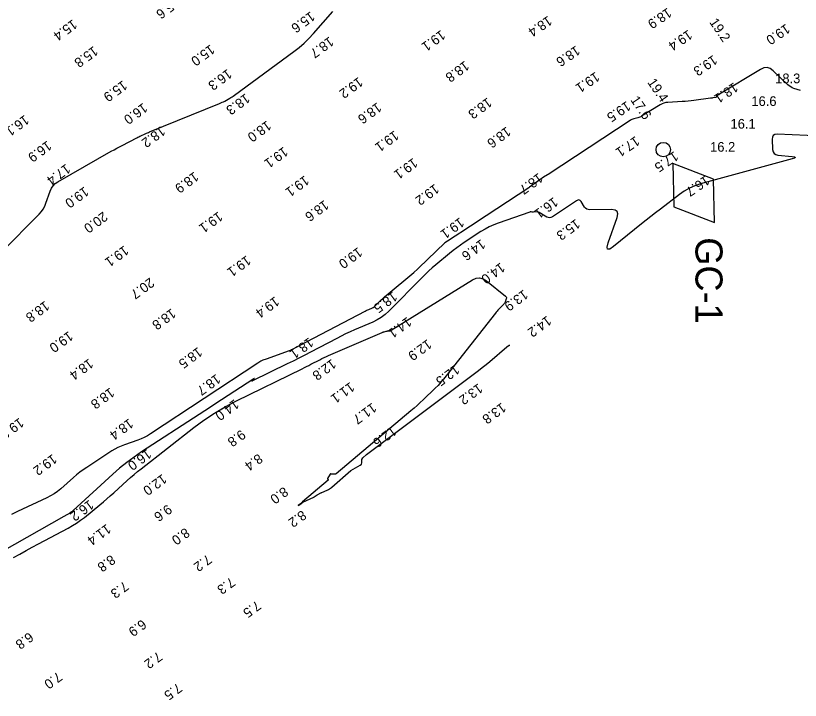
# Model space of a CAD drawing. Extents: x 824616 to 827440, y 158441 to 163197.
# Drawn here: x 826199.3 to 826605.2, y 159460.1 to 159814.3 of the extents above; entities that cross this region are included whole.
import ezdxf

# ---------------------------------------------------------------- set-up
doc = ezdxf.new("R2010")
doc.units = 0
for name, color, linetype in [('V-CHAN-CONT-EL14', 7, 'Continuous'), ('V-CHAN-CONT-EL16', 7, 'Continuous'), ('V-CHAN-CONT-EL18', 7, 'Continuous'), ('V-CHAN-NAID', 7, 'Continuous'), ('V-TOPO-SOUN', 7, 'Continuous')]:
    doc.layers.add(name, color=color, linetype=linetype)

msp = doc.modelspace()

# ---------------------------------------------------------------- linework, layer by layer
at = {"layer": 'V-CHAN-CONT-EL14'}
msp.add_lwpolyline([(826198.15, 159533.93), (826201.38, 159535.74), (826204.61, 159537.53), (826207.86, 159539.29), (826211.11, 159541.04), (826226.44, 159549.2), (826228.62, 159550.43), (826230.74, 159551.76), (826232.79, 159553.19), (826234.77, 159554.72), (826242.8, 159561.24), (826244.63, 159562.74), (826246.43, 159564.27), (826248.21, 159565.82), (826249.96, 159567.41), (826256.93, 159573.79), (826258.68, 159575.37), (826260.47, 159576.91), (826262.29, 159578.42), (826264.14, 159579.89), (826291.4, 159601.16), (826296.65, 159605.05), (826302.09, 159608.65), (826307.7, 159611.96), (826313.5, 159614.98), (826347.48, 159631.64), (826348.63, 159632.2), (826349.77, 159632.78), (826350.9, 159633.36), (826352.04, 159633.94), (826356.56, 159636.31), (826357.69, 159636.89), (826358.84, 159637.45), (826360, 159637.98), (826361.16, 159638.5), (826388.81, 159650.38), (826389.06, 159650.48), (826389.32, 159650.58), (826389.58, 159650.66), (826389.84, 159650.74), (826391, 159651.06), (826391.22, 159651.11), (826391.43, 159651.15), (826391.65, 159651.19), (826391.86, 159651.21), (826392.74, 159651.27), (826392.96, 159651.3), (826393.16, 159651.35), (826393.36, 159651.43), (826393.55, 159651.53), (826435.55, 159677.56), (826437.44, 159678.42), (826439.29, 159678.63), (826441.1, 159678.2), (826442.87, 159677.11), (826452.68, 159669.22), (826452.97, 159668.92), (826453.13, 159668.58), (826453.17, 159668.21), (826453.08, 159667.81), (826452.46, 159666.12), (826452.28, 159665.71), (826452.06, 159665.33), (826451.8, 159664.97), (826451.5, 159664.65), (826449.23, 159662.43), (826448.76, 159661.95), (826448.3, 159661.45), (826447.85, 159660.94), (826447.43, 159660.41), (826422, 159627.89), (826420.65, 159626.22), (826419.24, 159624.61), (826417.78, 159623.04), (826416.26, 159621.53), (826410.09, 159615.57), (826408.53, 159614.1), (826406.95, 159612.65), (826405.34, 159611.23), (826403.71, 159609.83), (826365.05, 159577.31), (826364.87, 159577.19), (826364.67, 159577.1), (826364.47, 159577.04), (826364.25, 159577.03), (826363.11, 159577.04), (826363, 159577.05), (826362.89, 159577.06), (826362.79, 159577.08), (826362.68, 159577.1), (826362.26, 159577.2), (826362.16, 159577.21), (826362.07, 159577.19), (826362, 159577.15), (826361.94, 159577.07), (826360.61, 159574.87), (826360.57, 159574.79), (826360.56, 159574.71), (826360.58, 159574.63), (826360.64, 159574.55), (826360.9, 159574.26), (826360.94, 159574.19), (826360.96, 159574.12), (826360.94, 159574.05), (826360.88, 159573.99), (826347.68, 159562.75), (826346.02, 159561.33), (826345.48, 159560.84), (826346.06, 159561.28), (826347.76, 159562.65), (826353.59, 159565.23), (826353.71, 159565.31), (826355.27, 159566.37), (826357.41, 159567.63), (826357.36, 159567.5), (826358, 159567.83), (826358.57, 159567.97), (826361.13, 159569.22), (826362.68, 159570.26), (826362.82, 159570.31), (826372.7, 159578.96), (826377.45, 159581.71), (826378.16, 159582.23), (826378.31, 159582.91), (826378.31, 159583.36), (826378.35, 159583.73), (826378.31, 159584.23), (826378.34, 159584.62), (826378.82, 159585.52), (826380.79, 159587.18), (826436.72, 159629.17), (826438.7, 159630.69), (826440.66, 159632.23), (826442.6, 159633.8), (826444.52, 159635.4), (826453.38, 159642.91), (826454.66, 159643.81), (826454.96, 159643.85)], dxfattribs=at)
at = {"layer": 'V-CHAN-CONT-EL16'}
msp.add_lwpolyline([(826616.44, 159752.06), (826593.19, 159752.93), (826592.04, 159752.81), (826591.24, 159752.34), (826590.78, 159751.54), (826590.67, 159750.39), (826590.91, 159745.1), (826591.13, 159743.93), (826591.67, 159743.05), (826592.51, 159742.47), (826593.67, 159742.18), (826600.98, 159741.42), (826602.23, 159741.21), (826602.66, 159740.94), (826602.28, 159740.6), (826601.08, 159740.2), (826553.51, 159727.23), (826550.59, 159726.29), (826547.8, 159725.07), (826545.15, 159723.58), (826542.63, 159721.83), (826532.81, 159714.28), (826530.37, 159712.38), (826527.93, 159710.47), (826525.5, 159708.55), (826523.09, 159706.61), (826508.58, 159694.9), (826506.64, 159693.59), (826505.54, 159693.48), (826505.28, 159694.55), (826505.86, 159696.82), (826510.43, 159709.93), (826510.79, 159711.71), (826510.42, 159712.98), (826509.34, 159713.73), (826507.54, 159713.97), (826496.26, 159713.88), (826495.46, 159713.96), (826494.75, 159714.22), (826494.14, 159714.66), (826493.63, 159715.28), (826491.76, 159718.12), (826491.26, 159718.68), (826490.7, 159718.95), (826490.09, 159718.92), (826489.41, 159718.59), (826476.95, 159710.23), (826476.22, 159709.86), (826475.48, 159709.72), (826474.74, 159709.82), (826473.99, 159710.15), (826470.05, 159712.48), (826469.76, 159712.63), (826469.45, 159712.73), (826469.14, 159712.78), (826468.81, 159712.78), (826467.13, 159712.66), (826466.98, 159712.66), (826466.83, 159712.66), (826466.67, 159712.67), (826466.52, 159712.68), (826465.91, 159712.76), (826465.76, 159712.77), (826465.61, 159712.76), (826465.46, 159712.74), (826465.32, 159712.7), (826448.9, 159707.03), (826446.56, 159706.14), (826444.29, 159705.11), (826442.1, 159703.94), (826439.97, 159702.63), (826431.32, 159696.94), (826429.38, 159695.62), (826427.48, 159694.25), (826425.62, 159692.83), (826423.79, 159691.35), (826416.58, 159685.35), (826414.79, 159683.82), (826413.05, 159682.26), (826411.34, 159680.65), (826409.67, 159679.01), (826392.28, 159661.42), (826390.41, 159659.71), (826388.41, 159658.19), (826386.27, 159656.88), (826384, 159655.77), (826374.61, 159651.74), (826372.27, 159650.71), (826369.96, 159649.63), (826367.66, 159648.52), (826365.39, 159647.35), (826351.83, 159640.26), (826348.81, 159638.7), (826345.78, 159637.15), (826342.74, 159635.62), (826339.69, 159634.12), (826321.76, 159625.33), (826321.54, 159625.24), (826321.45, 159625.23), (826321.48, 159625.32), (826321.64, 159625.5), (826322.54, 159626.39), (826322.71, 159626.56), (826322.75, 159626.63), (826322.67, 159626.61), (826322.47, 159626.48), (826305.74, 159615.46), (826302.86, 159613.57), (826299.98, 159611.68), (826297.1, 159609.8), (826294.21, 159607.92), (826264.38, 159588.6), (826260.48, 159585.95), (826256.69, 159583.15), (826253.03, 159580.19), (826249.48, 159577.07), (826228.92, 159558.23), (826228.75, 159558.08), (826228.58, 159557.92), (826228.4, 159557.78), (826228.22, 159557.63), (826227.52, 159557.06), (826227.34, 159556.92), (826227.15, 159556.79), (826226.96, 159556.67), (826226.76, 159556.55), (826225.37, 159555.81), (826225.07, 159555.65), (826224.77, 159555.49), (826224.48, 159555.33), (826224.18, 159555.16), (826179.28, 159529.82)], dxfattribs=at)
at = {"layer": 'V-CHAN-CONT-EL18'}
for points in [[(826191.93, 159691.89), (826211.47, 159711.7), (826212.56, 159712.94), (826213.5, 159714.27), (826214.28, 159715.7), (826214.91, 159717.23), (826217.1, 159723.53), (826217.76, 159725.02), (826218.64, 159726.31), (826219.75, 159727.42), (826221.09, 159728.34), (826248.73, 159744.15), (826250.13, 159744.94), (826251.54, 159745.72), (826252.96, 159746.48), (826254.38, 159747.23), (826261.85, 159751.13), (826262.4, 159751.41), (826262.95, 159751.68), (826263.51, 159751.94), (826264.06, 159752.2), (826266.31, 159753.22), (826266.87, 159753.47), (826267.43, 159753.72), (826268, 159753.96), (826268.57, 159754.19), (826304.79, 159768.9), (826305.47, 159769.19), (826306.13, 159769.49), (826306.78, 159769.81), (826307.43, 159770.15), (826309.99, 159771.56), (826310.62, 159771.92), (826311.24, 159772.3), (826311.85, 159772.7), (826312.45, 159773.12), (826343.1, 159795.74), (826345.84, 159797.88), (826348.46, 159800.16), (826350.95, 159802.57), (826353.31, 159805.13), (826363.26, 159816.5)], [(826605.35, 159775.6), (826601.88, 159776.73), (826601.04, 159777.06), (826600.25, 159777.48), (826599.51, 159777.98), (826598.82, 159778.56), (826591.15, 159785.85), (826589.61, 159786.97), (826588.01, 159787.45), (826586.35, 159787.31), (826584.61, 159786.55), (826563.41, 159773.65), (826563.29, 159773.57), (826563.17, 159773.51), (826563.04, 159773.44), (826562.92, 159773.38), (826562.34, 159773.11), (826562.25, 159773.06), (826562.17, 159773), (826562.09, 159772.93), (826562.02, 159772.85), (826561.68, 159772.4), (826561.66, 159772.37), (826561.65, 159772.34), (826561.64, 159772.31), (826561.64, 159772.27), (826561.63, 159772.14), (826561.63, 159772.11), (826561.61, 159772.09), (826561.59, 159772.07), (826561.56, 159772.06), (826559.91, 159771.78), (826559.62, 159771.73), (826559.33, 159771.69), (826559.05, 159771.64), (826558.76, 159771.6), (826550.2, 159770.43), (826548.67, 159770.24), (826547.15, 159770.08), (826545.61, 159769.95), (826544.08, 159769.85), (826536.6, 159769.46), (826535.58, 159769.34), (826534.6, 159769.1), (826533.66, 159768.74), (826532.75, 159768.26), (826523.09, 159762.31), (826522.63, 159762.05), (826522.16, 159761.83), (826521.67, 159761.64), (826521.16, 159761.49), (826519.1, 159760.95), (826518.6, 159760.8), (826518.11, 159760.61), (826517.64, 159760.37), (826517.19, 159760.1), (826474.83, 159732.2), (826474.36, 159731.97), (826472.4, 159730.85), (826470.37, 159729.38)], [(826470.37, 159729.38), (826465.08, 159725.55), (826464.67, 159725.19), (826437.23, 159707.11), (826435.9, 159706.24), (826434.58, 159705.37), (826433.26, 159704.51), (826431.93, 159703.65), (826426.63, 159700.21), (826425.3, 159699.35), (826423.98, 159698.49), (826422.66, 159697.62), (826421.33, 159696.75), (826407.78, 159683.83)], [(826340.78, 159640.98), (826340.83, 159640.98), (826340.94, 159641.03), (826341.54, 159641.32), (826341.68, 159641.39), (826341.83, 159641.46), (826341.97, 159641.54), (826342.12, 159641.61), (826380.11, 159661.48), (826380.56, 159661.71), (826381.02, 159661.93), (826381.49, 159662.15), (826381.95, 159662.36), (826383.83, 159663.16), (826384.29, 159663.38), (826384.71, 159663.65), (826385.11, 159663.95), (826385.49, 159664.29), (826388.41, 159667.25), (826389.03, 159667.86), (826389.65, 159668.45), (826390.3, 159669.02), (826390.95, 159669.58), (826405.29, 159681.51), (826407.21, 159683.17), (826407.71, 159683.75), (826407.78, 159683.83)], [(826340.78, 159640.98), (826328.83, 159636.67), (826327.19, 159636.07), (826326.02, 159635.53), (826324.58, 159634.55), (826268.97, 159597.92), (826267.41, 159596.96), (826265.8, 159596.11), (826264.14, 159595.35), (826262.43, 159594.7), (826255.49, 159592.3), (826253.78, 159591.65), (826252.12, 159590.89), (826250.52, 159590.03), (826248.96, 159589.08), (826236.01, 159580.56), (826234.21, 159579.33), (826232.46, 159578.04), (826230.75, 159576.69), (826229.09, 159575.29), (826222.53, 159569.54), (826220.85, 159568.16), (826219.08, 159566.92), (826217.24, 159565.8), (826215.31, 159564.8), (826200.24, 159557.7), (826197.1, 159556.15)]]:
    msp.add_lwpolyline(points, dxfattribs=at)
at = {"layer": 'V-CHAN-NAID'}
msp.add_lwpolyline([(826539.3, 159737.86), (826539.81, 159715.39), (826560.75, 159707.22), (826560.23, 159729.69)], close=True, dxfattribs=at)
msp.add_circle((826534.29, 159745.01), 3.74, dxfattribs=at)

# ---------------------------------------------------------------- texts
msp.add_text('GC-1', height=14, rotation=270, dxfattribs=at).set_placement((826550.97, 159699.65))
at = {"layer": 'V-TOPO-SOUN'}
for s, rotation, p in [('15.6 ', 216.2, (826281.92, 159823.96)), ('15.6 ', 216.2, (826351.82, 159816.76)), ('18.9 ', 214.2, (826536.52, 159818.62)), ('15.4 ', 216.2, (826228.79, 159812.66)), ('18.4 ', 214.2, (826474.66, 159814.46)), ('19.2 ', 304.2, (826557.96, 159810.96)), ('19.1 ', 216.2, (826419.29, 159807.14)), ('19.4 ', 214.2, (826547.21, 159807.23)), ('19.0 ', 214.2, (826597.76, 159810.32)), ('18.7 ', 216.2, (826361.55, 159803.72)), ('15.8 ', 216.2, (826239.57, 159798.82)), ('15.0 ', 216.2, (826299.98, 159799.63)), ('18.6 ', 214.2, (826489.14, 159799.05)), ('18.8 ', 216.2, (826431.63, 159791.2)), ('19.3 ', 214.2, (826560.15, 159794.19)), ('16.3 ', 216.2, (826308.87, 159787)), ('19.2 ', 216.2, (826376.66, 159782.82)), ('19.1 ', 214.2, (826499.24, 159785.48)), ('15.9 ', 216.2, (826254.68, 159781.08)), ('19.4 ', 304.2, (826525.88, 159779.84)), ('18.1 ', 214.2, (826570.89, 159780.01)), ('18.3 ', 216.2, (826318.16, 159774.32)), ('18.3 ', 216.2, (826443.38, 159772.19)), ('19.5 ', 214.2, (826515.37, 159770.35)), ('17.6 ', 304.2, (826517.11, 159770.75)), ('16.0 ', 216.2, (826265.17, 159769.41)), ('18.6 ', 216.2, (826386.28, 159769.66)), ('16.1 ', 216.2, (826203.92, 159763.21)), ('18.0 ', 216.2, (826329.21, 159760.28)), ('18.2 ', 216.2, (826274.39, 159757.38)), ('19.1 ', 216.2, (826395.2, 159755.15)), ('18.6 ', 216.2, (826453.17, 159757.15)), ('16.9 ', 216.2, (826215.57, 159749.85)), ('17.1 ', 214.2, (826519.95, 159752.23)), ('19.1 ', 216.2, (826337.89, 159746.74)), ('17.5 ', 214.2, (826540.02, 159744.42)), ('17.4 ', 216.2, (826225.31, 159737.93)), ('19.1 ', 216.2, (826404.95, 159740.96)), ('18.9 ', 216.2, (826291.62, 159733.81)), ('19.1 ', 216.2, (826348.8, 159731.88)), ('18.7 ', 216.2, (826469.73, 159733.15)), ('16.7 ', 214.2, (826556.15, 159731.85)), ('19.0 ', 216.2, (826234.79, 159726.11)), ('19.2 ', 216.2, (826416.07, 159727.5)), ('18.6 ', 216.2, (826358.95, 159719.16)), ('16.1 ', 216.2, (826477.62, 159720.68)), ('20.0 ', 216.2, (826244.53, 159713.16)), ('19.1 ', 216.2, (826304.1, 159713.19)), ('19.1 ', 216.2, (826429.05, 159710.14)), ('15.3 ', 216.2, (826489.04, 159709.38)), ('14.6 ', 216.2, (826440.02, 159698.89)), ('19.1 ', 216.2, (826255.4, 159695.61)), ('19.0 ', 216.2, (826376.38, 159694.74)), ('19.1 ', 216.2, (826318.68, 159690.47)), ('14.0 ', 216.2, (826450.15, 159686.81)), ('20.7 ', 216.2, (826268.69, 159679)), ('13.9 ', 216.2, (826462.08, 159672.81)), ('19.4 ', 216.2, (826333.38, 159669.26)), ('18.5 ', 216.2, (826394.43, 159671.78)), ('18.8 ', 216.2, (826214.43, 159667)), ('18.8 ', 216.2, (826279.85, 159663.06)), ('14.1 ', 216.2, (826401.83, 159658.7)), ('14.2 ', 216.2, (826474.16, 159659.29)), ('19.0 ', 216.2, (826226.69, 159651.31)), ('18.1 ', 216.2, (826351.05, 159648.08)), ('12.9 ', 216.2, (826412.26, 159647.11)), ('18.5 ', 216.2, (826293.55, 159643.07)), ('18.4 ', 216.2, (826237.16, 159637.12)), ('12.8 ', 216.2, (826362.78, 159636.92)), ('12.5 ', 216.2, (826426.63, 159633.98)), ('18.7 ', 216.2, (826302.99, 159629.15)), ('11.1 ', 216.2, (826372.31, 159624.97)), ('13.2 ', 216.2, (826438.63, 159624.29)), ('18.8 ', 216.2, (826248.1, 159622.09)), ('14.0 ', 216.2, (826312.51, 159616.1)), ('11.7 ', 216.2, (826383.69, 159614.26)), ('13.8 ', 216.2, (826450.68, 159614.32)), ('19.3 ', 216.2, (826201.22, 159606.51)), ('18.4 ', 216.2, (826257.86, 159606.1)), ('9.8', 216.2, (826315.89, 159600.35)), ('12.6 ', 216.2, (826394.09, 159602.22)), ('19.2 ', 216.2, (826218.35, 159587.72)), ('16.0 ', 216.2, (826267.23, 159590.34)), ('8.4', 216.2, (826324.73, 159587.94)), ('12.0 ', 216.2, (826275.15, 159577.39)), ('8.0', 216.2, (826337.94, 159570.78)), ('16.2 ', 216.2, (826237.38, 159564.06)), ('9.6', 216.2, (826277.81, 159561.69)), ('8.2', 216.2, (826347.35, 159558.66)), ('11.4 ', 216.2, (826246.3, 159551.56)), ('8.0', 216.2, (826286.96, 159549.56)), ('8.8', 216.2, (826248.54, 159535.59)), ('7.2', 216.2, (826298.38, 159535.78)), ('7.3', 216.2, (826310.48, 159524)), ('7.3', 216.2, (826255.37, 159521.92)), ('7.5', 216.2, (826323.86, 159511.9)), ('6.9', 216.2, (826264.6, 159502.18)), ('6.8', 216.2, (826206.14, 159495.57)), ('7.2', 216.2, (826272.79, 159485.51)), ('7.0', 216.2, (826220.98, 159475.05)), ('7.5', 216.2, (826283.01, 159469.26))]:
    msp.add_text(s, height=5, rotation=rotation, dxfattribs=at).set_placement(p)
for s, p in [('18.3 ', (826592.21, 159779.38)), ('16.6 ', (826579.9, 159767.61)), ('16.1 ', (826569.1, 159755.88)), ('16.2 ', (826558.54, 159743.93))]:
    msp.add_text(s, height=5, dxfattribs=at).set_placement(p)

doc.saveas('drawing.dxf')
